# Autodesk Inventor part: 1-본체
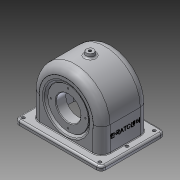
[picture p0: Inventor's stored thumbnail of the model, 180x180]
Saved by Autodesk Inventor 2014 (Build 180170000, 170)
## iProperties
Created: 2015-09
Part Number: 1-본체
Material: 알루미늄 6061
Document SubType Name: Modeling
Designer: Administrator
Density: 2.71 g/cm^3
Appearance: 알루미늄 - 평지
Mass: 677.087 g
Surface Area: 895.412 cm^2
Volume: 249.848 cm^3
Author: Administrator
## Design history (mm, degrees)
sketch "스케치1"
  geometry: L1 (57, 0)-(-57, 0); L2 (-57, 0)-(-57, -40); L3 (-57, -40)-(57, -40); L4 (57, -40)-(57, 0); L5 (70, -40)-(-70, -40); L6 (-70, -40)-(-70, -47); L7 (-70, -47)-(70, -47); L8 (70, -47)-(70, -40); A1 r 57 centre (0, 0) between (57, 0) and (40.608, -40); 6 further points
  constraints: 16 end point, 5 point on circle, 4 parallel, 4 point on line, 3 midpoint, 2 coincident, 2 horizontal, 2 perpendicular, 1 centre point
  dimensions: "d0" = 114 diameter of A1; "d1" = 7 distance of L5.end L6.end; "d2" = 47 distance between parallel lines of L1 L7; "d3" = 140 distance of L6.end L7.end
extrude "돌출1" new body sketch "스케치1" stored distance "d4" = 77; taper "d5" = 0 deg
extrude "돌출2" join sketch "스케치1" stored distance "d6" = 104; taper "d7" = 0 deg
fillet "모깎기1" dims "d12" = 14
feature "쉘1" dims "d13" = 7, "d14" = 5
sketch "스케치2"
  geometry: L1 (-38.5, 43.943)-(-38.5, 0); L2 (-38.5, 0)-(-19.5, 0); L3 (-19.5, 0)-(-19.5, 28); L4 (-19.5, 28)-(-38.5, 43.943); L5 (-38.5, 0)-(-38.5, 43) reference; L6 (24.5, 0)-(-24.5, 0) reference; L7 (-33.5, 33.22)-(-33.5, 5); L8 (-33.5, 5)-(-24.5, 5); L9 (-24.5, 5)-(-24.5, 25.668); L10 (-24.5, 25.668)-(-33.5, 33.22); L11 (-38.5, 37.416)-(-19.5, 21.473); 1 further point
  constraints: 18 end point, 3 point on line, 2 collinear, 2 parallel, 2 perpendicular, 1 midpoint, 1 vertical, 3 other
  dimensions: "d24" = 19 distance between parallel lines of L1 L3; "d25" = 50 deg angle of L3 L4; "d27" = 56 diameter of L3.end L2; "d28" = 5 distance between parallel lines of L4 L10
revolve "회전4" sketch "스케치2" stored, may be unused: angle "d29" = 90 deg
sketch "스케치10"
  geometry: L1 (113, -90.5)-(88.193, -90.5) reference; L2 (51.807, -90.5)-(27, -90.5) reference; L3 (30.253, -85.5)-(109.747, -85.5) reference; L4 (88.193, -90.5)-(51.807, -90.5); L5 (51.807, -90.5)-(51.807, -85.5); L6 (51.807, -85.5)-(88.193, -85.5); L7 (88.193, -85.5)-(88.193, -90.5); 1 further point
  constraints: 8 end point, 2 parallel, 1 horizontal, 1 perpendicular, 1 point on line
extrude "돌출6" join sketch "스케치10" stored distance "d94" = 10; taper "d95" = 0 deg
sketch "스케치4"
  geometry: L1 (-33.5, 39.747)-(-38.5, 43.943); L2 (-36.714, 35.917)-(-41.684, 40.087); L3 (-38.5, 43.943)-(-19.5, 28); L4 (-19.5, 28)-(-19.5, 20); L5 (-19.5, 20)-(-38.5, 20); L6 (-38.5, 20)-(-38.5, 43.943); L7 (-72.8, 0)-(72.8, 0) reference; L8 (-38.5, 37.416)-(-19.5, 21.473); L9 (-38.5, -40)-(-38.5, -9.054) reference; L10 (-33.5, 39.747)-(-38.47, 43.918) reference; 1 further point
  constraints: 14 end point, 3 collinear, 3 point on line, 2 perpendicular, 1 parallel, 1 vertical
  dimensions: "d30" = 5 distance between parallel lines of L1 L2; "d31" = 19 distance of L4.end L5.end; "d32" = 40 diameter of L5 L7; "d119" = 50 deg angle of L4 L3 (derived)
revolve "회전5" sketch "스케치4" stored, may be unused: angle "d34" = 90 deg
node "작업 평면2"
sketch "스케치5"
  geometry: C1 r 33 at (0, 0); 1 further point
  constraints: 1 centre point, 1 coincident
  dimensions: "d36" = 66 diameter of C1
extrude "돌출3" join sketch "스케치5" stored distance "d37" = 16; taper "d38" = 0 deg
sketch "스케치6"
  geometry: C1 r 31 at (0, 0); 1 further point
  constraints: 1 centre point, 1 coincident
  dimensions: "d39" = 62 diameter of C1
extrude "돌출4" join sketch "스케치6" distance "d40" = 10; taper "d41" = 0 deg
sketch "스케치13"
  geometry: C1 r 28 at (0, 0) reference; 1 further point
extrude "돌출7" cut sketch "스케치13" stored distance "d120" = 10; taper "d121" = 0 deg
hole "구멍1" diameter "d44" = 40; stored, may be unused: countersink angle "d48" = 90 deg, drill point angle "d50" = 118 deg; dims "d45" = 6, "d46" = 4, "d47" = 2, "d49" = 40, "d51" = 10, "d52" = 10
chamfer "모따기1" distance "d53" = 1; stored, may be unused: second distance "d54" = 2, angle "d55" = 45 deg
fillet "모깎기2" dims "d56" = 0.5
fillet "모깎기3" dims "d57" = 3
fillet "모깎기4" dims "d58" = 3
node "작업 평면4"
  node "작업 평면3"
sketch "스케치7"
  geometry: C1 r 6 at (0, 0); 1 further point
  constraints: 1 centre point, 1 coincident
  dimensions: "d60" = 12 diameter of C1
extrude "돌출5" join sketch "스케치7" stored distance "d61" = 10; taper "d62" = 10 deg
fillet "모깎기5" dims "d63" = 3
hole "구멍2" diameter "d66" = 4.459; stored, may be unused: countersink angle "d70" = 90 deg, drill point angle "d72" = 118 deg; dims "d64" = 10, "d65" = 10, "d67" = 15, "d68" = 4, "d69" = 2, "d71" = 40
fillet "모깎기6" dims "d73" = 7
sketch "스케치8"
  geometry: C1 r 2.5 at (0, 7); A1 r 7 centre (0, 7) between (-7, 7) and (0, 0) reference; 1 further point
  constraints: 1 centre point, 1 concentric
  dimensions: "d74" = 5 diameter of C1
hole "구멍3" sketch "스케치8" at (0, 7) diameter "d75" = 5; stored, may be unused: countersink angle "d79" = 90 deg, drill point angle "d81" = 118 deg; dims "d76" = 5, "d77" = 4, "d78" = 2, "d80" = 40
fillet "모깎기7" dims "d88" = 3
sketch "스케치9"
  geometry: L1 (12.171, 22.074)-(12.171, 26.926); L2 (12.171, 26.926)-(21.829, 26.926); L3 (21.829, 26.926)-(21.829, 22.074); L4 (21.829, 22.074)-(12.171, 22.074); L5 (0, 0)-(0, 49) reference; L6 (9.054, -14)-(40, -14) reference; L7 (47, -20.5)-(47, 69.5) reference; 4 further points
  constraints: 3 midpoint, 1 horizontal alignment, 1 vertical, 2 other
  dimensions: "d89" = 38.5 distance from line of L6 point (12.171, 24.5) (derived); "d90" = 30 distance from line of L7 point (17, 22.074)
feature "엠보싱1" sketch "스케치9" dims "d0" = 114, "d1" = 7, "d2" = 47, "d3" = 140, "d91" = 0.5, "d92" = 0
fillet "모깎기9" dims "d96" = 1
sketch "스케치11"
  geometry: L1 (0, 0)-(0, 28)
  constraints: 2 end point, 1 vertical
  dimensions: "d97" = 28 distance of L1.start L1.end
hole "구멍4" sketch "스케치11" at (0, 28) diameter "d98" = 2.459; stored, may be unused: countersink angle "d102" = 90 deg, drill point angle "d104" = 118 deg; dims "d99" = 7, "d100" = 4, "d101" = 2, "d103" = 9
sketch "스케치12"
  geometry: L1 (0, 0)-(0, -24)
  constraints: 2 end point, 1 vertical
  dimensions: "d108" = 24 distance of L1.start L1.end
hole "구멍5" sketch "스케치12" at (0, -24) diameter "d109" = 2.459; stored, may be unused: countersink angle "d113" = 90 deg, drill point angle "d115" = 118 deg; dims "d110" = 6, "d111" = 4, "d112" = 2, "d114" = 8
node "솔리드1"
pattern_linear "직사각형 패턴1" dims "d84" = 124, "d87" = 44
pattern_circular "원형 패턴1" dims angle "d106" = 360 deg
pattern_circular "원형 패턴2" dims angle "d117" = 360 deg
other parameters: "d35" = -16, "d59" = 6
